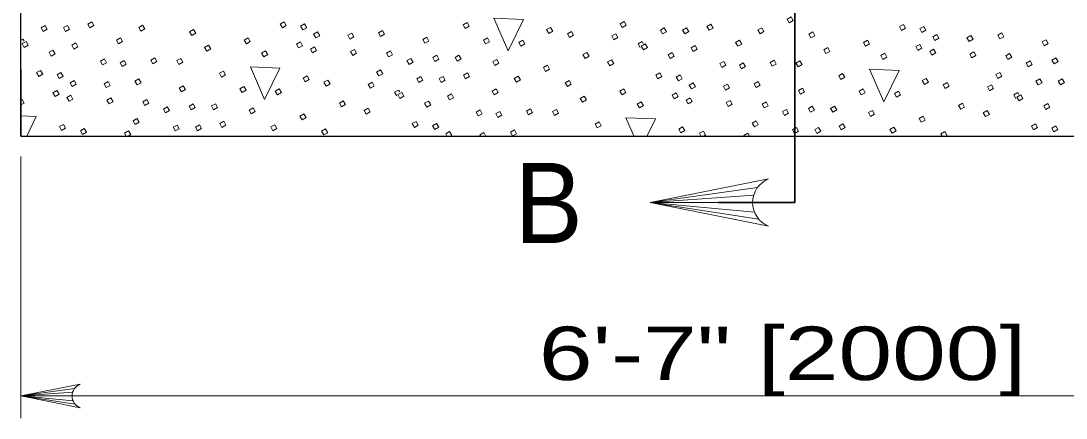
# Model space of a CAD drawing. Extents: x 750.7 to 784.7, y 860.1 to 882.1.
# Drawn here: x 754.003 to 757.13, y 862.108 to 863.297 of the extents above; entities that cross this region are included whole.
import ezdxf

# ---------------------------------------------------------------- set-up
doc = ezdxf.new("R2010")
doc.units = 0
doc.header["$LTSCALE"] = 0.064
doc.layers.add('1', color=7, linetype='Continuous', lineweight=13)

msp = doc.modelspace()

# ---------------------------------------------------------------- linework, layer by layer
at = {"layer": '1', "lineweight": 35}
for q in [(756.31867, 864.29933), (756.08967, 862.75308)]:
    msp.add_line((756.31867, 862.75308), q, dxfattribs=at)
at = {"layer": '1', "lineweight": 25}
for p, q in [((754.00275, 862.95208), (754.00275, 863.48375)), ((754.00275, 863.15042), (754.00275, 862.95208)), ((754.00275, 862.95208), (758.63458, 862.95208))]:
    msp.add_line(p, q, dxfattribs=at)
at = {"layer": '1'}
for p, q in [((754.00325, 863.22475), (754.00275, 863.22567)), ((755.85592, 863.21742), (755.84983, 863.22833)), ((755.12708, 863.07225), (755.121, 863.08317)), ((756.97975, 863.06492), (756.97367, 863.07583)), ((755.81317, 863.007), (755.83658, 862.95317)), ((754.31817, 862.95225), (754.31308, 862.96125)), ((755.27725, 862.95283), (755.27367, 862.95925)), ((755.3775, 862.95292), (755.37583, 862.95592)), ((755.47383, 862.953), (755.46775, 862.96375)), ((756.03742, 862.95333), (756.03333, 862.96058)), ((756.16608, 862.95342), (756.16575, 862.95392)), ((756.75842, 862.95375), (756.75525, 862.95933)), ((754.00275, 862.89058), (754.00275, 862.10817)), ((756.20642, 862.79792), (755.88583, 862.75308)), ((756.19558, 862.77575), (755.88583, 862.75308)), ((756.19225, 862.75308), (755.88583, 862.75308)), ((756.19792, 862.72425), (755.88583, 862.75308)), ((756.21017, 862.7035), (755.88583, 862.75308)), ((754.16308, 862.19675), (754.00275, 862.17433)), ((754.15767, 862.18567), (754.00275, 862.17433)), ((754.00275, 862.17433), (756.79983, 862.17433)), ((754.156, 862.17433), (754.00275, 862.17433)), ((754.15883, 862.15992), (754.00275, 862.17433)), ((754.165, 862.1495), (754.00275, 862.17433)), ((756.79983, 862.17433), (758.63458, 862.17433))]:
    msp.add_line(p, q, dxfattribs=at)
for points in [[(755.41808, 863.30467), (755.46058, 863.20725), (755.50625, 863.301)], [(756.29525, 863.30233), (756.30708, 863.309), (756.31342, 863.29775), (756.30158, 863.29108)], [(754.06333, 863.27625), (754.07517, 863.283), (754.0815, 863.27175), (754.06967, 863.265)], [(754.13, 863.27658), (754.14183, 863.28333), (754.14825, 863.27208), (754.13633, 863.26533)], [(754.20283, 863.28725), (754.21467, 863.29392), (754.221, 863.28275), (754.20917, 863.276)], [(754.35517, 863.27708), (754.367, 863.28383), (754.37333, 863.27258), (754.3615, 863.26583)], [(754.5075, 863.26433), (754.51942, 863.27108), (754.52575, 863.25983), (754.51392, 863.25308)], [(754.77858, 863.28708), (754.7905, 863.29383), (754.79683, 863.28258), (754.785, 863.27583)], [(754.83967, 863.281), (754.8515, 863.28767), (754.85783, 863.27642), (754.846, 863.26975)], [(755.07267, 863.26142), (755.08458, 863.26817), (755.09092, 863.25692), (755.079, 863.25017)], [(755.32575, 863.28525), (755.33758, 863.292), (755.34392, 863.28075), (755.33208, 863.27408)], [(755.57575, 863.27067), (755.58758, 863.27742), (755.59392, 863.26617), (755.58208, 863.25942)], [(755.79583, 863.2885), (755.80767, 863.29525), (755.814, 863.284), (755.80217, 863.27725)], [(755.916, 863.26892), (755.92783, 863.27567), (755.93417, 863.26442), (755.92233, 863.25767)], [(755.98267, 863.26925), (755.99458, 863.276), (756.00092, 863.26475), (755.989, 863.258)], [(756.0555, 863.27992), (756.06733, 863.28667), (756.07367, 863.27542), (756.06183, 863.26867)], [(756.20783, 863.26975), (756.21967, 863.2765), (756.226, 863.26525), (756.21417, 863.2585)], [(756.63133, 863.27975), (756.64317, 863.2865), (756.6495, 863.27525), (756.63767, 863.2685)], [(756.69233, 863.27367), (756.70417, 863.28033), (756.7105, 863.26908), (756.69867, 863.26242)], [(754.00625, 863.22875), (754.01808, 863.2355), (754.02442, 863.22425), (754.01258, 863.2175)], [(754.28858, 863.23942), (754.30042, 863.24617), (754.30675, 863.23492), (754.29492, 863.22817)], [(754.671, 863.2395), (754.68283, 863.24625), (754.68917, 863.235), (754.67733, 863.22825)], [(754.87858, 863.25692), (754.89042, 863.26367), (754.89675, 863.25242), (754.88492, 863.24567)], [(754.98075, 863.25367), (754.99258, 863.26033), (754.99892, 863.24908), (754.98708, 863.24242)], [(755.20542, 863.24117), (755.21725, 863.24783), (755.22358, 863.23658), (755.21175, 863.22992)], [(755.38683, 863.23892), (755.39867, 863.24567), (755.40508, 863.23442), (755.39317, 863.22767)], [(755.49267, 863.23217), (755.5045, 863.23892), (755.51092, 863.22767), (755.499, 863.22092)], [(755.63825, 863.25825), (755.65008, 863.265), (755.65642, 863.25375), (755.64458, 863.247)], [(755.77067, 863.25167), (755.7825, 863.25833), (755.78883, 863.24708), (755.777, 863.24042)], [(756.14125, 863.23208), (756.15308, 863.23883), (756.15942, 863.22758), (756.14758, 863.22083)], [(756.36017, 863.257), (756.37208, 863.26375), (756.37842, 863.2525), (756.36658, 863.24575)], [(756.52367, 863.23217), (756.5355, 863.23892), (756.54183, 863.22767), (756.53, 863.22092)], [(756.73125, 863.24958), (756.74308, 863.25633), (756.74942, 863.24508), (756.73758, 863.23833)], [(756.83342, 863.24633), (756.84525, 863.253), (756.85158, 863.24175), (756.83975, 863.23508)], [(756.92533, 863.25408), (756.93725, 863.26083), (756.94358, 863.24958), (756.93167, 863.24283)], [(757.05808, 863.23383), (757.06992, 863.2405), (757.07625, 863.22925), (757.06442, 863.22258)], [(754.08683, 863.20275), (754.09867, 863.20942), (754.105, 863.19817), (754.09317, 863.1915)], [(754.15517, 863.22392), (754.167, 863.23067), (754.17333, 863.21942), (754.1615, 863.21267)], [(754.5525, 863.21742), (754.56433, 863.22408), (754.57067, 863.21283), (754.55883, 863.20617)], [(754.72308, 863.20033), (754.73492, 863.207), (754.74125, 863.19583), (754.72942, 863.18908)], [(754.82742, 863.22717), (754.83925, 863.23383), (754.84567, 863.22258), (754.83375, 863.21592)], [(754.86917, 863.21258), (754.881, 863.21933), (754.88733, 863.20808), (754.8755, 863.20133)], [(754.98917, 863.20475), (755.001, 863.21142), (755.00733, 863.20017), (754.9955, 863.1935)], [(755.0965, 863.20008), (755.10833, 863.20683), (755.11467, 863.19558), (755.10283, 863.18883)], [(755.85892, 863.22142), (755.87075, 863.22817), (755.87708, 863.21692), (755.86525, 863.21017)], [(756.00783, 863.21658), (756.01967, 863.22333), (756.026, 863.21208), (756.01417, 863.20533)], [(756.40517, 863.21008), (756.417, 863.21675), (756.42333, 863.20558), (756.4115, 863.19883)], [(756.68008, 863.21983), (756.692, 863.2265), (756.69833, 863.21525), (756.68642, 863.20858)], [(756.72183, 863.20525), (756.73367, 863.212), (756.74, 863.20075), (756.72817, 863.194)], [(756.84183, 863.19742), (756.85367, 863.20408), (756.86, 863.19283), (756.84817, 863.18617)], [(754.24092, 863.17617), (754.25275, 863.18283), (754.25908, 863.17158), (754.24725, 863.16492)], [(754.29958, 863.17175), (754.3115, 863.17842), (754.31783, 863.16717), (754.306, 863.1605)], [(754.39158, 863.1795), (754.40342, 863.18625), (754.40975, 863.175), (754.39792, 863.16833)], [(754.46917, 863.17783), (754.481, 863.18458), (754.48733, 863.17333), (754.4755, 863.16658)], [(755.15775, 863.17783), (755.16958, 863.18458), (755.17592, 863.17333), (755.16408, 863.16658)], [(755.23483, 863.187), (755.24675, 863.19375), (755.25308, 863.1825), (755.24117, 863.17575)], [(755.30158, 863.18733), (755.31342, 863.19408), (755.31975, 863.18283), (755.30792, 863.17608)], [(755.41458, 863.17492), (755.42642, 863.18167), (755.43275, 863.17042), (755.42092, 863.16367)], [(755.68433, 863.19592), (755.69625, 863.20267), (755.70258, 863.19142), (755.69075, 863.18467)], [(755.75825, 863.174), (755.77008, 863.18067), (755.77642, 863.16942), (755.76458, 863.16275)], [(755.9395, 863.19542), (755.95133, 863.20217), (755.95767, 863.19092), (755.94583, 863.18417)], [(756.09358, 863.16883), (756.10542, 863.1755), (756.11175, 863.16425), (756.09992, 863.15758)], [(756.24425, 863.17225), (756.25608, 863.17892), (756.26242, 863.16767), (756.25058, 863.161)], [(756.32183, 863.1705), (756.33367, 863.17725), (756.34, 863.166), (756.32817, 863.15925)], [(756.57575, 863.193), (756.58758, 863.19975), (756.59392, 863.1885), (756.58208, 863.18175)], [(756.94917, 863.19275), (756.961, 863.1995), (756.96733, 863.18825), (756.9555, 863.1815)], [(757.01042, 863.1705), (757.02225, 863.17725), (757.02858, 863.166), (757.01675, 863.15925)], [(757.0875, 863.17967), (757.09942, 863.18642), (757.10575, 863.17517), (757.09392, 863.16842)], [(754.04983, 863.14192), (754.06167, 863.14867), (754.068, 863.13742), (754.05617, 863.13067)], [(754.11083, 863.13575), (754.12267, 863.1425), (754.129, 863.13125), (754.11717, 863.1245)], [(754.59692, 863.14008), (754.60875, 863.14683), (754.61508, 863.13558), (754.60325, 863.12883)], [(754.68925, 863.1595), (754.73183, 863.062), (754.77742, 863.15575)], [(755.067, 863.14333), (755.07892, 863.15), (755.08525, 863.13875), (755.07342, 863.13208)], [(755.32667, 863.13475), (755.33858, 863.14142), (755.34492, 863.13017), (755.33308, 863.1235)], [(755.56642, 863.15708), (755.57825, 863.16383), (755.58458, 863.15258), (755.57275, 863.14583)], [(755.9025, 863.13458), (755.91433, 863.14133), (755.92067, 863.13008), (755.90883, 863.12333)], [(756.15233, 863.16442), (756.16417, 863.17108), (756.1705, 863.15992), (756.15867, 863.15317)], [(756.54192, 863.15217), (756.5845, 863.05467), (756.63008, 863.14842)], [(756.91975, 863.136), (756.93158, 863.14267), (756.93792, 863.13142), (756.92608, 863.12475)], [(754.14975, 863.11175), (754.16167, 863.1185), (754.168, 863.10725), (754.15617, 863.1005)], [(754.25192, 863.10842), (754.26375, 863.11517), (754.27008, 863.10392), (754.25825, 863.09717)], [(754.34392, 863.11625), (754.35575, 863.123), (754.36208, 863.11175), (754.35025, 863.105)], [(754.84692, 863.1255), (754.85883, 863.13225), (754.86517, 863.121), (754.85333, 863.11425)], [(754.90942, 863.11308), (754.92133, 863.11975), (754.92767, 863.1085), (754.91583, 863.10183)], [(755.04192, 863.10642), (755.05375, 863.11317), (755.06008, 863.10192), (755.04825, 863.09517)], [(755.18717, 863.12375), (755.199, 863.13042), (755.20533, 863.11917), (755.1935, 863.1125)], [(755.25392, 863.12408), (755.26575, 863.13075), (755.27208, 863.11958), (755.26025, 863.11283)], [(755.479, 863.12458), (755.49083, 863.13133), (755.49717, 863.12008), (755.48533, 863.11333)], [(755.63142, 863.11183), (755.64325, 863.1185), (755.64958, 863.10725), (755.63775, 863.10058)], [(755.9635, 863.12842), (755.97533, 863.13517), (755.98167, 863.12392), (755.96983, 863.11725)], [(756.0025, 863.10442), (756.01433, 863.11117), (756.02067, 863.09992), (756.00883, 863.09317)], [(756.19658, 863.10892), (756.20842, 863.11567), (756.21475, 863.10442), (756.20292, 863.09767)], [(756.44958, 863.13275), (756.46142, 863.1395), (756.46775, 863.12825), (756.45592, 863.1215)], [(756.69958, 863.11817), (756.7115, 863.12492), (756.71783, 863.11367), (756.706, 863.10692)], [(756.76208, 863.10575), (756.774, 863.11242), (756.78033, 863.10125), (756.7685, 863.0945)], [(757.03983, 863.11642), (757.05167, 863.12308), (757.058, 863.11192), (757.04617, 863.10517)], [(757.10658, 863.11675), (757.11842, 863.12342), (757.12475, 863.11225), (757.11292, 863.1055)], [(754.09867, 863.08192), (754.1105, 863.08867), (754.11683, 863.07742), (754.105, 863.07067)], [(754.47667, 863.09592), (754.4885, 863.10267), (754.49483, 863.09142), (754.483, 863.08467)], [(754.65808, 863.09375), (754.66992, 863.10042), (754.67625, 863.08917), (754.66442, 863.0825)], [(754.76392, 863.087), (754.77575, 863.09375), (754.78208, 863.0825), (754.77025, 863.07575)], [(755.13017, 863.07625), (755.142, 863.083), (755.14833, 863.07175), (755.1365, 863.065)], [(755.41242, 863.08692), (755.42425, 863.09367), (755.43058, 863.08242), (755.41875, 863.07567)], [(755.79483, 863.087), (755.80675, 863.09375), (755.81308, 863.0825), (755.80125, 863.07575)], [(755.95133, 863.07458), (755.96317, 863.08133), (755.9695, 863.07008), (755.95767, 863.06333)], [(756.10458, 863.10108), (756.11642, 863.10783), (756.12283, 863.09658), (756.11092, 863.08983)], [(756.32933, 863.08858), (756.34117, 863.09533), (756.3475, 863.08408), (756.33567, 863.07733)], [(756.51075, 863.08642), (756.52258, 863.09308), (756.52892, 863.08183), (756.51708, 863.07517)], [(756.61658, 863.07967), (756.62842, 863.08642), (756.63475, 863.07517), (756.62292, 863.06842)], [(756.89458, 863.09908), (756.90642, 863.10583), (756.91275, 863.09458), (756.90092, 863.08792)], [(754.14033, 863.06742), (754.15225, 863.07417), (754.15858, 863.06292), (754.14675, 863.05617)], [(754.26033, 863.0595), (754.27217, 863.06625), (754.2785, 863.055), (754.26667, 863.04825)], [(754.36767, 863.05492), (754.3795, 863.06167), (754.38583, 863.05042), (754.374, 863.04367)], [(754.50608, 863.04183), (754.51792, 863.04858), (754.52425, 863.03733), (754.51242, 863.03058)], [(754.57275, 863.04217), (754.58458, 863.04892), (754.591, 863.03767), (754.57908, 863.03092)], [(754.95558, 863.05075), (754.96742, 863.0575), (754.97375, 863.04625), (754.96192, 863.0395)], [(755.21067, 863.05025), (755.2225, 863.05692), (755.22883, 863.04567), (755.217, 863.039)], [(755.279, 863.07142), (755.29083, 863.07817), (755.29717, 863.06692), (755.28533, 863.06017)], [(755.67633, 863.06492), (755.68825, 863.07158), (755.69458, 863.06033), (755.68275, 863.05367)], [(755.84692, 863.04783), (755.85875, 863.0545), (755.86508, 863.04325), (755.85325, 863.03658)], [(755.993, 863.06008), (756.00492, 863.06683), (756.01125, 863.05558), (755.99942, 863.04883)], [(756.113, 863.05217), (756.12483, 863.05892), (756.13125, 863.04767), (756.11933, 863.04092)], [(756.22033, 863.04758), (756.23217, 863.05433), (756.2385, 863.04308), (756.22667, 863.03633)], [(756.80825, 863.04342), (756.82008, 863.05017), (756.82642, 863.03892), (756.81458, 863.03217)], [(756.98283, 863.06892), (756.99467, 863.07567), (757.001, 863.06442), (756.98917, 863.05767)], [(757.06333, 863.04292), (757.07517, 863.04958), (757.0815, 863.03833), (757.06967, 863.03167)], [(754.42892, 863.03267), (754.44075, 863.03933), (754.44717, 863.02817), (754.43525, 863.02142)], [(754.68575, 863.02975), (754.69767, 863.03642), (754.704, 863.02525), (754.69208, 863.0185)], [(754.83767, 863.01192), (754.8495, 863.01867), (754.85583, 863.00742), (754.844, 863.00067)], [(755.0295, 863.02875), (755.04133, 863.0355), (755.04767, 863.02425), (755.03583, 863.0175)], [(755.36475, 863.02367), (755.37658, 863.03033), (755.38292, 863.01908), (755.37108, 863.01242)], [(755.4235, 863.01925), (755.43533, 863.02592), (755.44167, 863.01467), (755.42983, 863.008)], [(755.51542, 863.027), (755.52733, 863.03375), (755.53367, 863.0225), (755.52175, 863.01575)], [(755.593, 863.02533), (755.60492, 863.03208), (755.61125, 863.02083), (755.59942, 863.01408)], [(756.28158, 863.02533), (756.29342, 863.03208), (756.29983, 863.02083), (756.28792, 863.01408)], [(756.35875, 863.0345), (756.37058, 863.04125), (756.37692, 863.03), (756.36508, 863.02325)], [(756.42542, 863.03483), (756.43733, 863.04158), (756.44367, 863.03033), (756.43175, 863.02358)], [(756.53842, 863.02242), (756.55033, 863.02908), (756.55667, 863.01792), (756.54483, 863.01117)], [(756.88217, 863.02142), (756.894, 863.02817), (756.90033, 863.01692), (756.8885, 863.01025)], [(754.11817, 862.98033), (754.13, 862.98708), (754.13633, 862.97583), (754.1245, 862.96908)], [(754.33825, 862.99808), (754.35008, 863.00483), (754.35642, 862.99358), (754.34458, 862.98692)], [(754.45833, 862.97858), (754.47025, 862.98525), (754.47658, 862.974), (754.46475, 862.96733)], [(754.52508, 862.97892), (754.53692, 862.98558), (754.54325, 862.97433), (754.53142, 862.96767)], [(754.59792, 862.9895), (754.60975, 862.99625), (754.61608, 862.985), (754.60425, 862.97825)], [(754.75025, 862.97942), (754.76208, 862.98617), (754.76842, 862.97492), (754.75658, 862.96817)], [(755.17367, 862.98942), (755.1855, 862.99608), (755.19183, 862.98483), (755.18, 862.97817)], [(755.23467, 862.98325), (755.24658, 862.99), (755.25292, 862.97875), (755.241, 862.972)], [(755.72075, 862.98758), (755.73267, 862.99433), (755.739, 862.98308), (755.72708, 862.97633)], [(756.19092, 862.99083), (756.20275, 862.9975), (756.20908, 862.98625), (756.19725, 862.97958)], [(756.45058, 862.98217), (756.46242, 862.98892), (756.46875, 862.97767), (756.45692, 862.97092)], [(756.69033, 863.00458), (756.70217, 863.01133), (756.7085, 863.00008), (756.69667, 862.99333)], [(757.02633, 862.98208), (757.03817, 862.98875), (757.04458, 862.9775), (757.03267, 862.97083)], [(754.18067, 862.96792), (754.1925, 862.97458), (754.19883, 862.96333), (754.187, 862.95667)], [(754.90258, 862.96658), (754.91442, 862.97333), (754.92075, 862.96208), (754.90892, 862.95542)], [(755.97083, 862.973), (755.98267, 862.97975), (755.989, 862.9685), (755.97717, 862.96175)], [(756.31108, 862.97125), (756.32292, 862.97792), (756.32925, 862.96667), (756.31742, 862.96)], [(756.37775, 862.97158), (756.38958, 862.97825), (756.39592, 862.967), (756.38408, 862.96033)], [(756.60292, 862.97208), (756.61475, 862.97883), (756.62108, 862.96758), (756.60925, 862.96083)], [(757.08733, 862.97592), (757.09925, 862.98267), (757.10558, 862.97142), (757.09367, 862.96467)]]:
    msp.add_lwpolyline(points, close=True, dxfattribs=at)
for points in [[(754.00275, 863.23883), (754.009, 863.24233), (754.01225, 863.23667)], [(755.84983, 863.22833), (755.86167, 863.235), (755.86492, 863.22933)], [(755.121, 863.08317), (755.13283, 863.08983), (755.13608, 863.08417)], [(756.97367, 863.07583), (756.9855, 863.0825), (756.98875, 863.07683)], [(754.00275, 863.06), (754.00608, 863.06183), (754.01242, 863.05058), (754.00275, 863.04517)], [(754.02017, 862.95208), (754.04867, 863.01058), (754.00275, 863.0125)], [(755.87692, 862.95325), (755.90133, 863.00325), (755.81317, 863.007)], [(754.31308, 862.96125), (754.32492, 862.968), (754.33125, 862.95675), (754.32342, 862.95225)], [(755.27367, 862.95925), (755.2855, 862.96592), (755.29183, 862.95475), (755.28858, 862.95283)], [(755.37583, 862.95592), (755.38767, 862.96267), (755.39317, 862.95292)], [(755.46775, 862.96375), (755.47958, 862.97042), (755.48592, 862.95925), (755.47492, 862.953)], [(756.03333, 862.96058), (756.04517, 862.96725), (756.0515, 862.956), (756.04675, 862.95333)], [(756.16575, 862.95392), (756.17758, 862.96067), (756.18167, 862.95342)], [(756.75525, 862.95933), (756.76708, 862.966), (756.77342, 862.95475), (756.77167, 862.95375)], [(756.23992, 862.68225), (755.88583, 862.75308), (756.23992, 862.82392)], [(754.17983, 862.13892), (754.00275, 862.17433), (754.17983, 862.20975)]]:
    msp.add_lwpolyline(points, dxfattribs=at)
for centre, radius in [((756.26855, 862.75313), 0.07644), ((754.19414, 862.17435), 0.03822)]:
    msp.add_arc(centre, radius, 112.08782, 247.91395, dxfattribs=at)

# ---------------------------------------------------------------- texts
for s, height, width, p in [('B', 0.24, 0.95, (755.48017, 862.63192)), ('6\'-7" [2000]', 0.16, 1.35, (755.5525, 862.222))]:
    msp.add_text(s, height=height, dxfattribs=dict(at, width=width)).set_placement(p)

doc.saveas('drawing.dxf')
